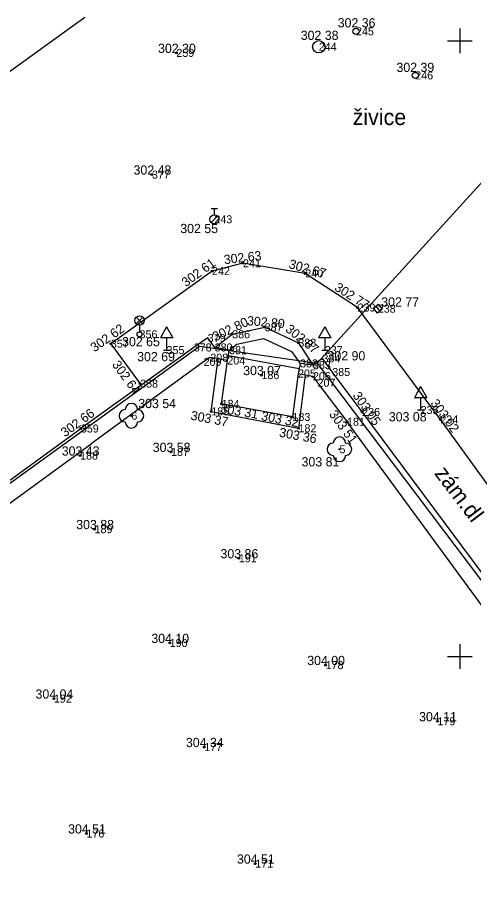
# Model space of a CAD drawing. Extents: x -492811 to -492366, y -1127107 to -1126748.
# Drawn here: x -492674.37 to -492659.56, y -1126887.82 to -1126859.24 of the extents above; entities that cross this region are included whole.
import ezdxf

# ---------------------------------------------------------------- set-up
doc = ezdxf.new("R2010")
doc.units = 0
for name, color, linetype in [('body', 7, 'Continuous'), ('doprava', 7, 'Continuous'), ('kanalizace', 7, 'Continuous'), ('katastrální mapa', 7, 'Continuous'), ('oplocení', 7, 'Continuous'), ('ostatní objekty', 7, 'Continuous'), ('plyn', 7, 'Continuous'), ('podrobný výškový bod', 7, 'Continuous'), ('popis ploch', 7, 'Continuous'), ('rozhraní ploch', 7, 'Continuous'), ('stromy', 7, 'Continuous'), ('síť', 7, 'Continuous'), ('veřejné osvětlení', 7, 'Continuous'), ('vodovod', 7, 'Continuous'), ('vstup na pozemek', 7, 'Continuous'), ('výšky', 7, 'Continuous'), ('čísla bodů', 7, 'Continuous')]:
    doc.layers.add(name, color=color, linetype=linetype)

msp = doc.modelspace()

# ---------------------------------------------------------------- linework, layer by layer
at = {"layer": 'body'}
for p, q in [((-492663.37, -1126859.691), (-492663.37, -1126859.691)), ((-492664.581, -1126860.193), (-492664.581, -1126860.193)), ((-492669.207, -1126860.392), (-492669.207, -1126860.392)), ((-492661.446, -1126861.123), (-492661.446, -1126861.123)), ((-492670.003, -1126864.346), (-492670.003, -1126864.346)), ((-492667.973, -1126865.797), (-492667.973, -1126865.797)), ((-492667.044, -1126867.225), (-492667.044, -1126867.225)), ((-492668.048, -1126867.479), (-492668.048, -1126867.479)), ((-492665.019, -1126867.556), (-492665.019, -1126867.556)), ((-492663.321, -1126868.664), (-492663.321, -1126868.664)), ((-492662.664, -1126868.7), (-492662.664, -1126868.7)), ((-492666.339, -1126869.305), (-492666.339, -1126869.305)), ((-492670.404, -1126869.533), (-492670.404, -1126869.533)), ((-492668.19, -1126869.651), (-492668.19, -1126869.651)), ((-492667.393, -1126869.532), (-492667.393, -1126869.532)), ((-492671.337, -1126869.838), (-492671.337, -1126869.838)), ((-492668.642, -1126869.96), (-492668.642, -1126869.96)), ((-492667.963, -1126869.959), (-492667.963, -1126869.959)), ((-492665.243, -1126869.808), (-492665.243, -1126869.808)), ((-492669.527, -1126870.045), (-492669.527, -1126870.045)), ((-492667.493, -1126870.049), (-492667.493, -1126870.049)), ((-492664.386, -1126870.045), (-492664.386, -1126870.045)), ((-492668.322, -1126870.428), (-492668.322, -1126870.428)), ((-492668.105, -1126870.29), (-492668.105, -1126870.29)), ((-492667.552, -1126870.384), (-492667.552, -1126870.384)), ((-492665.189, -1126870.479), (-492665.189, -1126870.479)), ((-492664.772, -1126870.535), (-492664.772, -1126870.535)), ((-492664.461, -1126870.315), (-492664.461, -1126870.315)), ((-492665.256, -1126870.806), (-492665.256, -1126870.806)), ((-492664.143, -1126870.757), (-492664.143, -1126870.757)), ((-492666.443, -1126870.859), (-492666.443, -1126870.859)), ((-492664.77, -1126870.893), (-492664.77, -1126870.893)), ((-492664.62, -1126871.105), (-492664.62, -1126871.105)), ((-492670.385, -1126871.137), (-492670.385, -1126871.137)), ((-492667.737, -1126871.792), (-492667.737, -1126871.792)), ((-492670.67, -1126872.178), (-492670.67, -1126872.178)), ((-492668.073, -1126872.036), (-492668.073, -1126872.036)), ((-492665.436, -1126872.217), (-492665.436, -1126872.217)), ((-492663.17, -1126872.055), (-492663.17, -1126872.055)), ((-492661.272, -1126871.991), (-492661.272, -1126871.991)), ((-492663.663, -1126872.372), (-492663.663, -1126872.372)), ((-492660.631, -1126872.299), (-492660.631, -1126872.299)), ((-492672.31, -1126872.592), (-492672.31, -1126872.592)), ((-492665.239, -1126872.585), (-492665.239, -1126872.585)), ((-492669.38, -1126873.355), (-492669.38, -1126873.355)), ((-492663.909, -1126873.268), (-492663.909, -1126873.268)), ((-492672.336, -1126873.473), (-492672.336, -1126873.473)), ((-492671.865, -1126875.863), (-492671.865, -1126875.863)), ((-492667.179, -1126876.81), (-492667.179, -1126876.81)), ((-492669.425, -1126879.56), (-492669.425, -1126879.56)), ((-492664.361, -1126880.278), (-492664.361, -1126880.278)), ((-492673.188, -1126881.368), (-492673.188, -1126881.368)), ((-492660.726, -1126882.105), (-492660.726, -1126882.105)), ((-492668.301, -1126882.942), (-492668.301, -1126882.942)), ((-492672.129, -1126885.749), (-492672.129, -1126885.749)), ((-492666.643, -1126886.729), (-492666.643, -1126886.729))]:
    msp.add_line(p, q, dxfattribs=at)
at = {"layer": 'doprava'}
for p, q in [((-492669.527, -1126869.285), (-492669.727, -1126869.645)), ((-492669.527, -1126869.285), (-492669.327, -1126869.645)), ((-492664.386, -1126869.285), (-492664.586, -1126869.645)), ((-492664.386, -1126869.285), (-492664.186, -1126869.645)), ((-492669.327, -1126869.645), (-492669.727, -1126869.645)), ((-492669.527, -1126869.645), (-492669.527, -1126870.045)), ((-492664.186, -1126869.645), (-492664.586, -1126869.645)), ((-492664.386, -1126869.645), (-492664.386, -1126870.045)), ((-492669.627, -1126870.045), (-492669.427, -1126870.045)), ((-492664.486, -1126870.045), (-492664.286, -1126870.045)), ((-492661.272, -1126871.231), (-492661.472, -1126871.591)), ((-492661.272, -1126871.231), (-492661.072, -1126871.591)), ((-492661.072, -1126871.591), (-492661.472, -1126871.591)), ((-492661.272, -1126871.591), (-492661.272, -1126871.991)), ((-492661.372, -1126871.991), (-492661.172, -1126871.991))]:
    msp.add_line(p, q, dxfattribs=at)
at = {"layer": 'kanalizace'}
msp.add_line((-492662.728, -1126868.623), (-492662.6, -1126868.777), dxfattribs=at)
msp.add_lwpolyline([(-492662.651, -1126868.559), (-492662.523, -1126868.713), (-492662.677, -1126868.841), (-492662.805, -1126868.687)], close=True, dxfattribs=at)
msp.add_circle((-492664.581, -1126860.193), 0.2, dxfattribs=at)
at = {"layer": 'katastrální mapa'}
for p, q in [((-492688.96, -1126871.33), (-492672.18, -1126859.23)), ((-492664.63, -1126870.47), (-492654.92, -1126859.79)), ((-492697.4, -1126890.84), (-492668.46, -1126869.92)), ((-492668.46, -1126869.92), (-492664.63, -1126870.47)), ((-492664.63, -1126870.47), (-492648.16, -1126892.3))]:
    msp.add_line(p, q, dxfattribs=at)
at = {"layer": 'oplocení'}
for p, q in [((-492668.19, -1126869.651), (-492668.642, -1126869.96)), ((-492667.963, -1126869.959), (-492668.19, -1126869.651)), ((-492668.642, -1126869.96), (-492672.31, -1126872.592)), ((-492667.493, -1126870.049), (-492667.963, -1126869.959)), ((-492667.552, -1126870.384), (-492667.493, -1126870.049)), ((-492668.322, -1126870.428), (-492671.977, -1126873.092)), ((-492668.105, -1126870.29), (-492668.322, -1126870.428)), ((-492667.552, -1126870.384), (-492668.105, -1126870.29)), ((-492665.189, -1126870.479), (-492665.256, -1126870.806)), ((-492664.772, -1126870.535), (-492665.189, -1126870.479)), ((-492664.461, -1126870.315), (-492664.772, -1126870.535)), ((-492664.143, -1126870.757), (-492664.461, -1126870.315)), ((-492665.256, -1126870.806), (-492664.77, -1126870.893)), ((-492663.17, -1126872.055), (-492664.143, -1126870.757)), ((-492664.77, -1126870.893), (-492664.62, -1126871.105)), ((-492664.62, -1126871.105), (-492663.663, -1126872.372)), ((-492658.298, -1126878.614), (-492663.17, -1126872.055)), ((-492658.361, -1126879.603), (-492663.663, -1126872.372)), ((-492676.164, -1126875.397), (-492672.31, -1126872.592)), ((-492675.813, -1126875.883), (-492671.977, -1126873.092))]:
    msp.add_line(p, q, dxfattribs=at)
at = {"layer": 'ostatní objekty'}
for p, q in [((-492667.393, -1126869.532), (-492666.339, -1126869.305)), ((-492666.339, -1126869.305), (-492665.243, -1126869.808)), ((-492667.963, -1126869.959), (-492667.393, -1126869.532)), ((-492667.243, -1126869.858), (-492666.379, -1126869.672)), ((-492666.379, -1126869.672), (-492665.472, -1126870.088)), ((-492667.493, -1126870.049), (-492667.243, -1126869.858)), ((-492665.243, -1126869.808), (-492664.772, -1126870.535)), ((-492665.472, -1126870.088), (-492665.189, -1126870.479)), ((-492668.073, -1126872.036), (-492667.849, -1126870.333)), ((-492667.737, -1126871.792), (-492667.552, -1126870.384)), ((-492665.256, -1126870.806), (-492665.436, -1126872.217)), ((-492665.018, -1126870.849), (-492665.239, -1126872.585)), ((-492665.436, -1126872.217), (-492667.737, -1126871.792)), ((-492668.073, -1126872.036), (-492665.239, -1126872.585))]:
    msp.add_line(p, q, dxfattribs=at)
at = {"layer": 'plyn'}
msp.add_circle((-492663.37, -1126859.691), 0.1, dxfattribs=at)
at = {"layer": 'podrobný výškový bod'}
for centre in [(-492669.207, -1126860.392), (-492670.003, -1126864.346), (-492667.044, -1126867.225), (-492668.048, -1126867.479), (-492665.019, -1126867.556), (-492663.321, -1126868.664), (-492666.339, -1126869.305), (-492667.393, -1126869.532), (-492671.337, -1126869.838), (-492665.243, -1126869.808), (-492670.385, -1126871.137), (-492666.443, -1126870.859), (-492667.737, -1126871.792), (-492668.073, -1126872.036), (-492665.436, -1126872.217), (-492663.17, -1126872.055), (-492663.663, -1126872.372), (-492660.631, -1126872.299), (-492672.31, -1126872.592), (-492665.239, -1126872.585), (-492669.38, -1126873.355), (-492672.336, -1126873.473), (-492671.865, -1126875.863), (-492667.179, -1126876.81), (-492669.425, -1126879.56), (-492664.361, -1126880.278), (-492673.188, -1126881.368), (-492660.726, -1126882.105), (-492668.301, -1126882.942), (-492672.129, -1126885.749), (-492666.643, -1126886.729)]:
    msp.add_circle(centre, 0.03, dxfattribs=at)
at = {"layer": 'rozhraní ploch'}
for p, q in [((-492667.044, -1126867.225), (-492668.048, -1126867.479)), ((-492665.019, -1126867.556), (-492667.044, -1126867.225)), ((-492668.048, -1126867.479), (-492671.337, -1126869.838)), ((-492663.321, -1126868.664), (-492665.019, -1126867.556)), ((-492660.631, -1126872.299), (-492663.321, -1126868.664)), ((-492671.337, -1126869.838), (-492670.35, -1126871.185)), ((-492658.157, -1126875.711), (-492660.631, -1126872.299))]:
    msp.add_line(p, q, dxfattribs=at)
at = {"layer": 'stromy'}
for centre in [(-492670.67, -1126872.178), (-492663.909, -1126873.268)]:
    msp.add_circle(centre, 0.02, dxfattribs=at)
for centre, start, end in [((-492670.67, -1126871.978), 360, 180), ((-492670.87, -1126872.178), 90, 270), ((-492670.47, -1126872.178), 270, 90), ((-492670.67, -1126872.378), 180, 0), ((-492664.109, -1126873.268), 90, 270), ((-492663.909, -1126873.068), 360, 180), ((-492663.709, -1126873.268), 270, 90), ((-492663.909, -1126873.468), 180, 0)]:
    msp.add_arc(centre, 0.2, start, end, dxfattribs=at)
at = {"layer": 'síť'}
for p, q in [((-492660, -1126859.6), (-492660, -1126860.4)), ((-492660.4, -1126860), (-492659.6, -1126860)), ((-492660, -1126879.6), (-492660, -1126880.4)), ((-492660.4, -1126880), (-492659.6, -1126880))]:
    msp.add_line(p, q, dxfattribs=at)
at = {"layer": 'veřejné osvětlení'}
for p, q in [((-492670.51, -1126869.189), (-492670.298, -1126868.977)), ((-492670.51, -1126868.977), (-492670.298, -1126869.189)), ((-492670.404, -1126869.233), (-492670.404, -1126869.453))]:
    msp.add_line(p, q, dxfattribs=at)
for centre, radius in [((-492670.404, -1126869.083), 0.15), ((-492670.404, -1126869.533), 0.08)]:
    msp.add_circle(centre, radius, dxfattribs=at)
at = {"layer": 'vodovod'}
for p, q in [((-492668.073, -1126865.447), (-492667.873, -1126865.447)), ((-492667.973, -1126865.647), (-492667.973, -1126865.447)), ((-492667.867, -1126865.691), (-492668.079, -1126865.903))]:
    msp.add_line(p, q, dxfattribs=at)
for centre, radius in [((-492661.446, -1126861.123), 0.1), ((-492667.973, -1126865.797), 0.15)]:
    msp.add_circle(centre, radius, dxfattribs=at)
at = {"layer": 'vstup na pozemek'}
msp.add_line((-492667.523, -1126870.217), (-492665.222, -1126870.643), dxfattribs=at)

# ---------------------------------------------------------------- texts
at = {"layer": 'popis ploch'}
msp.add_text('živice', height=0.52, dxfattribs=at).set_placement((-492663.48, -1126862.736))
msp.add_text('zám.dl', height=0.52, rotation=307.4503, dxfattribs=at).set_placement((-492660.845, -1126874.058))
at = {"layer": 'výšky'}
for s, p in [('302 36 ', (-492663.966, -1126859.564)), ('302 38 ', (-492665.167, -1126859.97)), ('302 30 ', (-492669.803, -1126860.392)), ('302 39 ', (-492662.057, -1126861.012)), ('302 48 ', (-492670.599, -1126864.346)), ('302 55 ', (-492669.081, -1126866.246)), ('302 77 ', (-492662.551, -1126868.631)), ('302 65 ', (-492670.971, -1126869.921)), ('302 69 ', (-492670.482, -1126870.407)), ('302 90 ', (-492664.296, -1126870.381)), ('303 07 ', (-492667.039, -1126870.859)), ('303 54 ', (-492670.446, -1126871.93)), ('303 08 ', (-492662.305, -1126872.362)), ('303 58 ', (-492669.976, -1126873.355)), ('303 43 ', (-492672.932, -1126873.473)), ('303 81 ', (-492665.14, -1126873.825)), ('303 88 ', (-492672.461, -1126875.863)), ('303 86 ', (-492667.775, -1126876.81)), ('304 10 ', (-492670.021, -1126879.56)), ('304 00 ', (-492664.957, -1126880.278)), ('304 04 ', (-492673.784, -1126881.368)), ('304 11 ', (-492661.322, -1126882.105)), ('304 34 ', (-492668.897, -1126882.942)), ('304 51 ', (-492672.725, -1126885.749)), ('304 51 ', (-492667.239, -1126886.729))]:
    msp.add_text(s, height=0.3, dxfattribs=at).set_placement(p)
for s, rotation, p in [('302 63 ', 6.5188, (-492667.648, -1126867.258)), ('302 61 ', 35.9869, (-492668.898, -1126868.006)), ('302 67 ', 344.339, (-492665.576, -1126867.377)), ('302 77 ', 327.4896, (-492664.096, -1126868.083)), ('302 80 ', 25.5452, (-492667.945, -1126869.766)), ('302 80 ', 355.1614, (-492666.923, -1126869.236)), ('302 62 ', 35.1191, (-492671.868, -1126870.123)), ('302 87 ', 321.1876, (-492665.688, -1126869.414)), ('302 64 ', 306.0841, (-492671.313, -1126870.519)), ('303 05 ', 305.2545, (-492663.494, -1126871.528)), ('303 02 ', 306.5651, (-492660.969, -1126871.774)), ('302 66 ', 35.9618, (-492672.829, -1126872.884)), ('303 31 ', 350.8925, (-492667.786, -1126872.085)), ('303 37 ', 349.4705, (-492668.759, -1126872.306)), ('303 32 ', 349.2082, (-492666.467, -1126872.321)), ('303 51 ', 306.0275, (-492664.263, -1126872.131)), ('303 36 ', 349.4706, (-492665.886, -1126872.855))]:
    msp.add_text(s, height=0.3, rotation=rotation, dxfattribs=at).set_placement(p)
at = {"layer": 'čísla bodů'}
for s, p in [('245', (-492663.37, -1126859.821)), ('244', (-492664.581, -1126860.323)), ('259', (-492669.207, -1126860.522)), ('246', (-492661.446, -1126861.253)), ('377', (-492670.003, -1126864.476)), ('243', (-492667.973, -1126865.927)), ('241', (-492667.044, -1126867.355)), ('242', (-492668.048, -1126867.609)), ('240', (-492665.019, -1126867.686)), ('239', (-492663.321, -1126868.794)), ('238', (-492662.664, -1126868.83)), ('387', (-492666.339, -1126869.435)), ('356', (-492670.404, -1126869.663)), ('379', (-492668.19, -1126869.781)), ('386', (-492667.393, -1126869.662)), ('388', (-492665.243, -1126869.938)), ('357', (-492671.337, -1126869.968)), ('355', (-492669.527, -1126870.175)), ('378', (-492668.642, -1126870.09)), ('380', (-492667.963, -1126870.089)), ('381', (-492667.493, -1126870.179)), ('237', (-492664.386, -1126870.175)), ('208', (-492668.105, -1126870.42)), ('204', (-492667.552, -1126870.514)), ('384', (-492664.461, -1126870.445)), ('209', (-492668.322, -1126870.558)), ('382', (-492665.189, -1126870.609)), ('383', (-492664.772, -1126870.665)), ('186', (-492666.443, -1126870.989)), ('205', (-492665.256, -1126870.936)), ('206', (-492664.77, -1126871.023)), ('385', (-492664.143, -1126870.887)), ('358', (-492670.385, -1126871.267)), ('207', (-492664.62, -1126871.235)), ('184', (-492667.737, -1126871.922)), ('185', (-492668.073, -1126872.166)), ('236', (-492663.17, -1126872.185)), ('235', (-492661.272, -1126872.121)), ('6', (-492670.67, -1126872.308)), ('183', (-492665.436, -1126872.347)), ('181', (-492663.663, -1126872.502)), ('234', (-492660.631, -1126872.429)), ('359', (-492672.31, -1126872.722)), ('182', (-492665.239, -1126872.715)), ('188', (-492672.336, -1126873.603)), ('187', (-492669.38, -1126873.485)), ('5', (-492663.909, -1126873.398)), ('189', (-492671.865, -1126875.993)), ('191', (-492667.179, -1126876.94)), ('190', (-492669.425, -1126879.69)), ('178', (-492664.361, -1126880.408)), ('192', (-492673.188, -1126881.498)), ('179', (-492660.726, -1126882.235)), ('177', (-492668.301, -1126883.072)), ('176', (-492672.129, -1126885.879)), ('171', (-492666.643, -1126886.859))]:
    msp.add_text(s, height=0.26, dxfattribs=at).set_placement(p)

doc.saveas('drawing.dxf')
